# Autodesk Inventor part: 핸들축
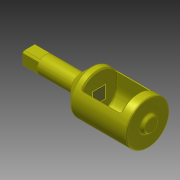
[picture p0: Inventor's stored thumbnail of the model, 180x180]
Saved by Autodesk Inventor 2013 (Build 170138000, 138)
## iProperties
Created: 2018-01
Part Number: 핸들축
Material: 강철, 연강
Document SubType Name: Modeling
Designer: mduedu
Density: 1 g/cm^3
Author: mduedu
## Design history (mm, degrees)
sketch "스케치1"
  geometry: L1 (0, 0)-(-109, 0); L2 (-46, -7.5)-(0, -7.5); L3 (0, -7.5)-(0, 0); L4 (-106, -19)-(-46, -19); L5 (-46, -19)-(-46, -7.5); L6 (-106, -7.5)-(-106, -19); L7 (-109, -5.768)-(-106, -7.5); L8 (-109, -5.768)-(-109, 0)
  constraints: 16 end point, 2 parallel, 1 horizontal, 1 vertical
  dimensions: "d8" = 15 diameter of L2 L1; "d43" = 46 distance between parallel lines of L3 L5; "d47" = 60 distance between parallel lines of L5 L6; "d63" = 3 distance between parallel lines of L6 L8; "d77" = 38 diameter of L4 L1; "d78" = 15 diameter of L6.start L1; "d79" = 30 deg angle of L1 L7
revolve "회전1" sketch "스케치1" stored, may be unused: angle "d9" = 90 deg
sketch "스케치4"
  geometry: L1 (-6, -6)-(-4.5, -6); L2 (6, -6)-(6, -4.5); L3 (6, 6)-(4.5, 6); L4 (-6, 6)-(-6, 4.5); L5 (-6, -6)-(6, 6); L6 (6, -6)-(-6, 6); L7 (-4.5, 6)-(-6, 6); L8 (-6, 4.5)-(-6, -4.5); L9 (-6, -4.5)-(-6, -6); L10 (-4.5, -6)-(4.5, -6); L11 (4.5, -6)-(6, -6); L12 (6, -4.5)-(6, 4.5); L13 (6, 4.5)-(6, 6); L14 (4.5, 6)-(-4.5, 6); C1 r 7.5 at (0, 0) reference; 2 further points
  constraints: 28 end point, 18 parallel, 9 perpendicular, 3 horizontal, 2 midpoint, 1 coincident, 11 other
  dimensions: "d20" = 12 distance of L4.start L3.start; "d21" = 12 distance of L3.start L2.start (= d20)
extrude "돌출2" cut sketch "스케치4" distance "d22" = 15; taper "d23" = 0 deg
chamfer "모따기2" distance "d24" = 1; stored, may be unused: second distance "d25" = 2, angle "d26" = 45 deg
sketch "스케치5"
  geometry: 2 further points
  constraints: 1 coincident
hole "구멍1" sketch "스케치5" at (5, 4.153) diameter "d27" = 2.459; stored, may be unused: countersink angle "d31" = 90 deg, drill point angle "d33" = 120 deg; dims "d28" = 6.9, "d29" = 4, "d30" = 2, "d32" = 8.4
node "작업 평면1"
sketch "스케치9"
  geometry: L1 (10, 4.153)-(10, 15.815); L2 (-20, 4.153)-(-20, 15.815); A1 r 15 centre (-5, 4.153) between (-20, 4.153) and (10, 4.153); A2 r 19 centre (-5, 4.153) between (10, 15.815) and (-20, 15.815) reference; 1 further point
  constraints: 4 end point, 4 point on circle, 2 tangent, 1 centre point, 1 coincident, 1 concentric, 1 parallel, 1 vertical
  dimensions: "d76" = 4 radial gap between concentric circles of A2 A1
extrude "돌출4" cut sketch "스케치9" distance "d73" = 34; taper "d74" = 0 deg
chamfer "모따기3" distance "d44" = 10; stored, may be unused: second distance "d45" = 2, angle "d46" = 45 deg
fillet "모깎기4" dims "d80" = 1
chamfer "모따기5" distance "d81" = 1; stored, may be unused: second distance "d82" = 2, angle "d83" = 45 deg
node "솔리드1"
other parameters: "d75" = -64
